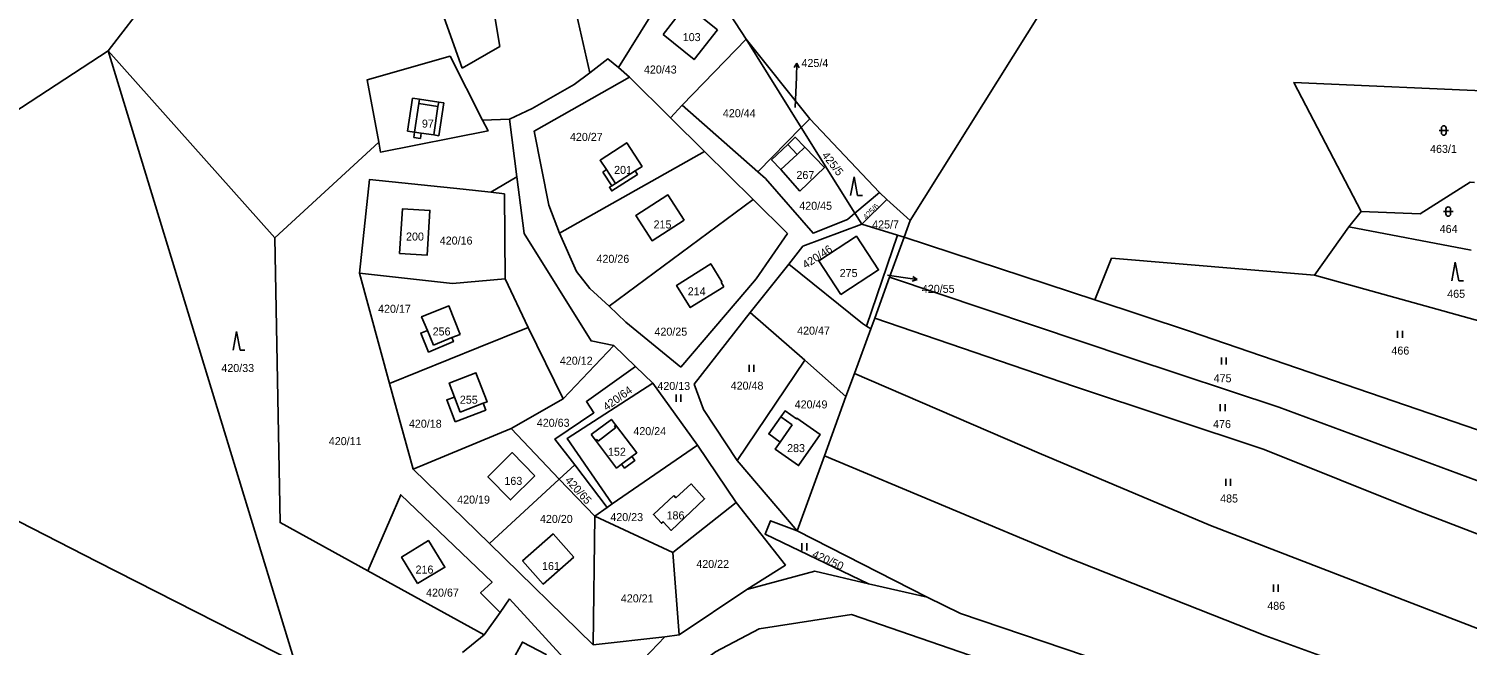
# Model space of a CAD drawing. Extents: x -7483133 to -743169, y -11317770 to -1127091.
# Drawn here: x -748944.8 to -748639.3, y -1130557.3 to -1130426.4 of the extents above; entities that cross this region are included whole.
import ezdxf

# ---------------------------------------------------------------- set-up
doc = ezdxf.new("R2010")
doc.units = 0
for name, color, linetype in [('Hranice parcel', 7, 'Continuous'), ('Parcelní čísla', 7, 'Continuous'), ('Pop  PČ popisy', 7, 'Continuous'), ('Vnitřní kresba', 7, 'Continuous'), ('Značky kultur', 7, 'Continuous')]:
    doc.layers.add(name, color=color, linetype=linetype)

msp = doc.modelspace()

# ---------------------------------------------------------------- linework, layer by layer
at = {"layer": 'Hranice parcel'}
for p, q in [((-748902.2, -1130397.64), (-748927.95, -1130431.02)), ((-748849.48, -1130401.7), (-748844.76, -1130430.14)), ((-748819.51, -1130434.58), (-748804.37, -1130410.14)), ((-748792.44, -1130428.53), (-748804.37, -1130410.14)), ((-748805.98, -1130442.59), (-748792.44, -1130428.53)), ((-748778.89, -1130445.44), (-748792.44, -1130428.53)), ((-748780.72, -1130447.3), (-748792.44, -1130428.53)), ((-748927.95, -1130431.02), (-748892.55, -1130470.72)), ((-748927.95, -1130431.02), (-748888.26, -1130560.86)), ((-748844.76, -1130430.14), (-748852.71, -1130434.75)), ((-748817.21, -1130436.65), (-748819.51, -1130434.58)), ((-748808.51, -1130445.24), (-748817.21, -1130436.65)), ((-748805.98, -1130442.59), (-748808.51, -1130445.24)), ((-748789.95, -1130456.7), (-748805.98, -1130442.59)), ((-748848.41, -1130445.73), (-748842.67, -1130445.58)), ((-748841.12, -1130457.78), (-748842.67, -1130445.58)), ((-748801.29, -1130452.44), (-748808.51, -1130445.24)), ((-748789.95, -1130456.7), (-748780.72, -1130447.3)), ((-748780.72, -1130447.3), (-748778.89, -1130445.44)), ((-748769.34, -1130465.53), (-748780.72, -1130447.3)), ((-748764.11, -1130461.14), (-748778.89, -1130445.44)), ((-748892.55, -1130470.72), (-748870.46, -1130450.45)), ((-748832.08, -1130469.75), (-748801.29, -1130452.44)), ((-748801.29, -1130452.44), (-748790.91, -1130462.62)), ((-748788.31, -1130458.17), (-748789.95, -1130456.7)), ((-748852.5, -1130460.44), (-748846.67, -1130461.06)), ((-748846.67, -1130461.06), (-748841.12, -1130457.78)), ((-748839.58, -1130469.86), (-748841.12, -1130457.78)), ((-748846.67, -1130461.06), (-748843.74, -1130461.37)), ((-748843.74, -1130461.37), (-748843.6, -1130479.46)), ((-748790.91, -1130462.62), (-748821.52, -1130485.28)), ((-748790.91, -1130462.62), (-748783.62, -1130469.82)), ((-748769.34, -1130465.53), (-748764.11, -1130461.14)), ((-748767.88, -1130467.87), (-748762.56, -1130462.59)), ((-748762.56, -1130462.59), (-748764.11, -1130461.14)), ((-748757.6, -1130467.05), (-748762.56, -1130462.59)), ((-748769.34, -1130465.53), (-748770.9, -1130466.83)), ((-748767.88, -1130467.87), (-748769.34, -1130465.53)), ((-748664.43, -1130468.41), (-748661.8, -1130465.15)), ((-748760.27, -1130470.2), (-748767.88, -1130467.87)), ((-748757.6, -1130467.05), (-748758.89, -1130470.62)), ((-748671.7, -1130478.68), (-748664.43, -1130468.41)), ((-748664.43, -1130468.41), (-748638.43, -1130473.4)), ((-748766.84, -1130489.51), (-748760.27, -1130470.2)), ((-748761.98, -1130479.13), (-748758.89, -1130470.62)), ((-748758.89, -1130470.62), (-748760.27, -1130470.2)), ((-748758.89, -1130470.62), (-748718.34, -1130483.88)), ((-748868.14, -1130501.65), (-748874.54, -1130478.26)), ((-748791.56, -1130486.57), (-748783.35, -1130476.32)), ((-748843.6, -1130479.46), (-748838.72, -1130489.81)), ((-748797.15, -1130481.13), (-748797.74, -1130480.18)), ((-748765.12, -1130487.78), (-748761.98, -1130479.13)), ((-748803.45, -1130501.81), (-748791.56, -1130486.57)), ((-748791.56, -1130486.57), (-748779.98, -1130496.71)), ((-748765.94, -1130490.05), (-748765.12, -1130487.78)), ((-748838.72, -1130489.81), (-748831.25, -1130504.91)), ((-748769.41, -1130499.53), (-748765.94, -1130490.05)), ((-748765.94, -1130490.05), (-748766.84, -1130489.51)), ((-748831.25, -1130504.91), (-748820.54, -1130493.62)), ((-748820.54, -1130493.62), (-748815.91, -1130498.09)), ((-748779.98, -1130496.71), (-748794.31, -1130518)), ((-748771.22, -1130504.47), (-748779.98, -1130496.71)), ((-748815.91, -1130498.09), (-748812.25, -1130501.61)), ((-748771.22, -1130504.47), (-748769.41, -1130499.53)), ((-748863.15, -1130519.89), (-748868.14, -1130501.65)), ((-748812.25, -1130501.61), (-748802.76, -1130514.74)), ((-748831.25, -1130504.91), (-748842.3, -1130511.21)), ((-748775.79, -1130517.06), (-748771.22, -1130504.47)), ((-748842.3, -1130511.21), (-748863.15, -1130519.89)), ((-748832.1, -1130521.99), (-748842.3, -1130511.21)), ((-748802.76, -1130514.74), (-748820.87, -1130527.26)), ((-748802.76, -1130514.74), (-748794.57, -1130526.92)), ((-748794.31, -1130518), (-748781.55, -1130532.95)), ((-748781.55, -1130532.95), (-748775.79, -1130517.06)), ((-748846.93, -1130535.69), (-748863.15, -1130519.89)), ((-748832.1, -1130521.99), (-748828.83, -1130518.95)), ((-748828.83, -1130518.95), (-748821.95, -1130528)), ((-748846.93, -1130535.69), (-748832.1, -1130521.99)), ((-748824.58, -1130529.82), (-748832.1, -1130521.99)), ((-748820.87, -1130527.26), (-748821.95, -1130528)), ((-748794.57, -1130526.92), (-748807.97, -1130537.59)), ((-748824.94, -1130557.15), (-748824.58, -1130529.82)), ((-748821.95, -1130528), (-748824.58, -1130529.82)), ((-748807.97, -1130537.59), (-748824.58, -1130529.82)), ((-748754, -1130547.08), (-748781.55, -1130532.95)), ((-748824.94, -1130557.15), (-748846.93, -1130535.69)), ((-748806.63, -1130555.06), (-748807.97, -1130537.59)), ((-748848.06, -1130555.08), (-748872.79, -1130541.46)), ((-748806.63, -1130555.06), (-748792.29, -1130545.43)), ((-748766.4, -1130544.2), (-748754, -1130547.08)), ((-748842.68, -1130547.42), (-748844.69, -1130550.29)), ((-748822.02, -1130569.92), (-748842.68, -1130547.42)), ((-748844.69, -1130550.29), (-748848.06, -1130555.08)), ((-748848.06, -1130555.08), (-748852.67, -1130558.78)), ((-748809.68, -1130555.47), (-748806.63, -1130555.06)), ((-748809.68, -1130555.47), (-748824.94, -1130557.15))]:
    msp.add_line(p, q, dxfattribs=at)
for points in [[(-748668.63, -1130323.88), (-748723.49, -1130412.55), (-748757.6, -1130467.05)], [(-748825.64, -1130435.7), (-748830.6, -1130413.85), (-748827.29, -1130401.09), (-748824.29, -1130394.55), (-748817.71, -1130391.16)], [(-748852.71, -1130434.75), (-748864.73, -1130401.17), (-748858.73, -1130399.01)], [(-748798.53, -1130426.57), (-748805.14, -1130421.28), (-748810.06, -1130427.6)], [(-748810.06, -1130427.6), (-748803.47, -1130432.9), (-748798.53, -1130426.57)], [(-749070.43, -1130467.11), (-748982.99, -1130466.97), (-748927.95, -1130431.02)], [(-748848.41, -1130445.73), (-748855.31, -1130432.18), (-748872.92, -1130437.22), (-748870.46, -1130450.45)], [(-748825.64, -1130435.7), (-748821.76, -1130432.75), (-748819.51, -1130434.58)], [(-748842.67, -1130445.58), (-748837.83, -1130443.26), (-748828.93, -1130438.2), (-748825.64, -1130435.7)], [(-748817.21, -1130436.65), (-748837.42, -1130448.09), (-748834.32, -1130463.8), (-748832.08, -1130469.75)], [(-748661.8, -1130465.15), (-748676.09, -1130437.74), (-748631.31, -1130439.73)], [(-748870.46, -1130450.45), (-748870.08, -1130452.52), (-748847.24, -1130448.03), (-748848.41, -1130445.73)], [(-748822.89, -1130456.78), (-748820.97, -1130459.7), (-748821.47, -1130460.02), (-748820.98, -1130460.78), (-748815.5, -1130457.27), (-748815.97, -1130456.53), (-748814.52, -1130455.58), (-748817.78, -1130450.55), (-748823.43, -1130454.26), (-748822.1, -1130456.26), (-748822.89, -1130456.78)], [(-748781, -1130460.83), (-748775.78, -1130455.82), (-748779.97, -1130451.47), (-748781.98, -1130449.37), (-748783.6, -1130450.93), (-748787.01, -1130454.2), (-748785.04, -1130456.25), (-748781, -1130460.83)], [(-748874.54, -1130478.26), (-748872.39, -1130458.34), (-748852.5, -1130460.44)], [(-748770.9, -1130466.83), (-748778.22, -1130469.78), (-748788.31, -1130458.17)], [(-748661.8, -1130465.15), (-748649.27, -1130465.67), (-748638.63, -1130458.96), (-748637.75, -1130459.01)], [(-748805.57, -1130466.96), (-748809.03, -1130461.64), (-748815.82, -1130465.97), (-748812.39, -1130471.35), (-748805.57, -1130466.96)], [(-748866.07, -1130474.04), (-748860.16, -1130474.4), (-748859.58, -1130464.94), (-748865.44, -1130464.59), (-748866.07, -1130474.04)], [(-749070.43, -1130467.11), (-749012.81, -1130497.2), (-748930.34, -1130539.46), (-748888.26, -1130560.86)], [(-748783.35, -1130476.32), (-748780.36, -1130472.52), (-748767.88, -1130467.87)], [(-748892.55, -1130470.72), (-748891.42, -1130531.21), (-748872.79, -1130541.46)], [(-748820.54, -1130493.62), (-748825.34, -1130492.64), (-748839.58, -1130469.86)], [(-748821.52, -1130485.28), (-748825.63, -1130481.5), (-748828.48, -1130477.93), (-748832.08, -1130469.75)], [(-748783.62, -1130469.82), (-748790.29, -1130479.46), (-748792.26, -1130481.76), (-748806.27, -1130498.24)], [(-748772.28, -1130482.78), (-748764.3, -1130477.55), (-748768.99, -1130470.4), (-748776.95, -1130475.63), (-748772.28, -1130482.78)], [(-748718.34, -1130483.88), (-748714.81, -1130475.07), (-748671.7, -1130478.68)], [(-748874.54, -1130478.26), (-748854.82, -1130480.43), (-748843.6, -1130479.46)], [(-748797.74, -1130480.18), (-748797.55, -1130480.06), (-748799.94, -1130476.26), (-748807.21, -1130480.86), (-748804.28, -1130485.57), (-748797.15, -1130481.13)], [(-748783.35, -1130476.32), (-748767.74, -1130488.96), (-748766.84, -1130489.51)], [(-748671.7, -1130478.68), (-748633.74, -1130489.24), (-748618.21, -1130483.5)], [(-748761.98, -1130479.13), (-748710.91, -1130496.25), (-748679.26, -1130506.7), (-748621.93, -1130527.97)], [(-748718.34, -1130483.88), (-748698.29, -1130490.59), (-748629.43, -1130514.15)], [(-748853.13, -1130491.26), (-748855.56, -1130485.21), (-748861.36, -1130487.49), (-748860.13, -1130490.42), (-748861.54, -1130490.99), (-748859.85, -1130495.02), (-748854.59, -1130492.79), (-748854.96, -1130491.92), (-748853.13, -1130491.26)], [(-748806.27, -1130498.24), (-748817.98, -1130488.65), (-748821.52, -1130485.28)], [(-748765.12, -1130487.78), (-748722.68, -1130502.34), (-748682.4, -1130515.73), (-748650.26, -1130528.57), (-748607.86, -1130544.88)], [(-748868.14, -1130501.65), (-748849.28, -1130494.06), (-748838.72, -1130489.81)], [(-748854.2, -1130509.79), (-748847.71, -1130507.33), (-748848.25, -1130505.89), (-748847.44, -1130505.58), (-748849.81, -1130499.38), (-748855.49, -1130501.59), (-748854.37, -1130504.59), (-748856.01, -1130505.15), (-748854.2, -1130509.79)], [(-748828.83, -1130518.95), (-748833.02, -1130513.48), (-748824.76, -1130507.89), (-748826.36, -1130505.51), (-748815.91, -1130498.09)], [(-748769.41, -1130499.53), (-748730.21, -1130516.5), (-748693.83, -1130531.8), (-748627.18, -1130557.56), (-748603.84, -1130566.17), (-748577.63, -1130576.56)], [(-748812.25, -1130501.61), (-748830.46, -1130513.37), (-748820.87, -1130527.26)], [(-748794.31, -1130518), (-748801.5, -1130507.17), (-748803.45, -1130501.81)], [(-748816.7, -1130517.18), (-748815.67, -1130516.4), (-748820.14, -1130510.48), (-748821.04, -1130509.29), (-748825.32, -1130512.52)], [(-748785.03, -1130508.74), (-748784.15, -1130507.49), (-748781.75, -1130509.19), (-748781.63, -1130509.04), (-748776.67, -1130512.52), (-748781.3, -1130519.11), (-748786.27, -1130515.61), (-748785.21, -1130514.11), (-748787.62, -1130512.4), (-748785.03, -1130508.74)], [(-748825.32, -1130512.52), (-748824.39, -1130513.73), (-748819.95, -1130519.63), (-748818.86, -1130518.81), (-748818.22, -1130519.65), (-748816.06, -1130518.02), (-748816.7, -1130517.18)], [(-748837.33, -1130521.27), (-748842.14, -1130516.36), (-748847.28, -1130521.51), (-748842.48, -1130526.4), (-748837.33, -1130521.27)], [(-748775.79, -1130517.06), (-748724.37, -1130538.57), (-748682.28, -1130555.19), (-748652.69, -1130565.92), (-748602.7, -1130584.94), (-748579.32, -1130593.13)], [(-748807.77, -1130525.47), (-748812.13, -1130529.47), (-748810.42, -1130531.37), (-748810.07, -1130531.04), (-748808.34, -1130532.87), (-748801.24, -1130526.14), (-748804.12, -1130523), (-748807.33, -1130525.95), (-748807.77, -1130525.47)], [(-748872.79, -1130541.46), (-748865.77, -1130525.3), (-748846.38, -1130543.87), (-748848.82, -1130546.16), (-748844.69, -1130550.29)], [(-748794.57, -1130526.92), (-748784.09, -1130540.23), (-748792.29, -1130545.43)], [(-748829.04, -1130538.57), (-748833.41, -1130533.62), (-748839.91, -1130539.35), (-748835.51, -1130544.26), (-748829.04, -1130538.57)], [(-748766.4, -1130544.2), (-748788.4, -1130533.64), (-748787.24, -1130530.81), (-748781.55, -1130532.95)], [(-748862.21, -1130544.17), (-748856.41, -1130540.69), (-748859.91, -1130535.03), (-748865.59, -1130538.53), (-748862.21, -1130544.17)], [(-748792.29, -1130545.43), (-748777.8, -1130541.55), (-748766.4, -1130544.2)], [(-748694.25, -1130568.39), (-748746.89, -1130550.49), (-748754, -1130547.08)], [(-748671.54, -1130609.27), (-748689.21, -1130588.28), (-748698.85, -1130579.03), (-748711.73, -1130570.87), (-748770.07, -1130550.7), (-748789.66, -1130553.8), (-748798.91, -1130558.69), (-748806.83, -1130564.57), (-748827.25, -1130594.48)], [(-748843.04, -1130562.3), (-748837.93, -1130565), (-748834.89, -1130559.25), (-748839.93, -1130556.59), (-748843.04, -1130562.3)], [(-748822.02, -1130569.92), (-748818.59, -1130564.8), (-748809.68, -1130555.47)]]:
    msp.add_lwpolyline(points, dxfattribs=at)
at = {"layer": 'Pop  PČ popisy'}
for p, q in [((-748781.66, -1130433.62), (-748782.19, -1130434.6)), ((-748781.76, -1130436.62), (-748781.66, -1130433.62)), ((-748781.66, -1130433.62), (-748781.19, -1130434.64)), ((-748781.98, -1130443.1), (-748781.76, -1130436.62)), ((-748762.38, -1130478.64), (-748759.07, -1130479.14)), ((-748759.07, -1130479.14), (-748756.11, -1130479.61)), ((-748756.11, -1130479.61), (-748757.17, -1130479.95)), ((-748756.11, -1130479.61), (-748757.02, -1130478.96))]:
    msp.add_line(p, q, dxfattribs=at)
at = {"layer": 'Vnitřní kresba'}
for p, q in [((-748864.32, -1130448.09), (-748863.29, -1130441.1)), ((-748861.79, -1130441.32), (-748863.29, -1130441.1)), ((-748861.79, -1130441.32), (-748861.93, -1130442.25)), ((-748857.7, -1130441.93), (-748861.79, -1130441.32)), ((-748857.89, -1130442.87), (-748857.7, -1130441.93)), ((-748856.66, -1130442.08), (-748857.7, -1130441.93)), ((-748857.69, -1130449.07), (-748856.66, -1130442.08)), ((-748861.93, -1130442.25), (-748862.83, -1130448.3)), ((-748861.93, -1130442.25), (-748857.89, -1130442.87)), ((-748858.72, -1130448.9), (-748857.89, -1130442.87)), ((-748862.83, -1130448.3), (-748864.32, -1130448.09)), ((-748863, -1130449.44), (-748862.83, -1130448.3)), ((-748863, -1130449.44), (-748861.6, -1130449.68)), ((-748862.83, -1130448.3), (-748861.43, -1130448.51)), ((-748861.43, -1130448.51), (-748861.6, -1130449.68)), ((-748858.72, -1130448.9), (-748861.43, -1130448.51)), ((-748857.69, -1130449.07), (-748858.72, -1130448.9)), ((-748783.6, -1130450.93), (-748781.59, -1130453.02)), ((-748781.59, -1130453.02), (-748785.04, -1130456.25)), ((-748781.59, -1130453.02), (-748779.97, -1130451.47)), ((-748822.1, -1130456.26), (-748820.16, -1130459.19)), ((-748820.16, -1130459.19), (-748815.97, -1130456.53)), ((-748820.97, -1130459.7), (-748820.16, -1130459.19)), ((-748860.13, -1130490.42), (-748858.82, -1130493.54)), ((-748858.82, -1130493.54), (-748854.96, -1130491.92)), ((-748853.18, -1130507.76), (-748854.37, -1130504.59)), ((-748853.18, -1130507.76), (-748848.25, -1130505.89)), ((-748785.03, -1130508.74), (-748782.61, -1130510.45)), ((-748820.09, -1130511.05), (-748823.86, -1130513.93)), ((-748820.14, -1130510.48), (-748820.38, -1130510.66)), ((-748820.38, -1130510.66), (-748820.09, -1130511.05)), ((-748782.61, -1130510.45), (-748785.21, -1130514.11)), ((-748824.15, -1130513.55), (-748824.39, -1130513.73)), ((-748823.86, -1130513.93), (-748824.15, -1130513.55)), ((-748816.7, -1130517.18), (-748818.86, -1130518.81))]:
    msp.add_line(p, q, dxfattribs=at)
at = {"layer": 'Značky kultur'}
for p, q in [((-748645.25, -1130447.95), (-748643.25, -1130447.95)), ((-748644.75, -1130447.45), (-748644.75, -1130448.45)), ((-748643.75, -1130448.45), (-748643.75, -1130447.45)), ((-748769.49, -1130457.79), (-748770.24, -1130461.79)), ((-748768.74, -1130461.79), (-748769.49, -1130457.79)), ((-748768.74, -1130461.79), (-748767.74, -1130461.79)), ((-748644.29, -1130465.16), (-748642.29, -1130465.16)), ((-748643.79, -1130464.66), (-748643.79, -1130465.66)), ((-748642.79, -1130465.66), (-748642.79, -1130464.66)), ((-748641.81, -1130475.88), (-748642.56, -1130479.88)), ((-748641.06, -1130479.88), (-748641.81, -1130475.88)), ((-748641.06, -1130479.88), (-748640.06, -1130479.88)), ((-748900.64, -1130490.63), (-748901.39, -1130494.63)), ((-748899.89, -1130494.63), (-748900.64, -1130490.63)), ((-748654.05, -1130491.99), (-748654.05, -1130490.49)), ((-748653.05, -1130491.99), (-748653.05, -1130490.49)), ((-748899.89, -1130494.63), (-748898.89, -1130494.63)), ((-748691.45, -1130497.67), (-748691.45, -1130496.17)), ((-748690.45, -1130497.67), (-748690.45, -1130496.17)), ((-748791.81, -1130499.23), (-748791.81, -1130497.73)), ((-748790.81, -1130499.23), (-748790.81, -1130497.73)), ((-748807.29, -1130505.55), (-748807.29, -1130504.05)), ((-748806.29, -1130505.55), (-748806.29, -1130504.05)), ((-748691.71, -1130507.54), (-748691.71, -1130506.04)), ((-748690.71, -1130507.54), (-748690.71, -1130506.04)), ((-748690.52, -1130523.4), (-748690.52, -1130521.9)), ((-748689.52, -1130523.4), (-748689.52, -1130521.9)), ((-748780.56, -1130537.12), (-748780.56, -1130535.62)), ((-748779.56, -1130537.12), (-748779.56, -1130535.62)), ((-748680.4, -1130545.89), (-748680.4, -1130544.39)), ((-748679.4, -1130545.89), (-748679.4, -1130544.39))]:
    msp.add_line(p, q, dxfattribs=at)
for centre, start, end in [((-748644.25, -1130447.45), 0, 180), ((-748644.25, -1130448.45), 180, 359.9879), ((-748643.29, -1130464.66), 0, 180), ((-748643.29, -1130465.66), 180, 359.9879)]:
    msp.add_arc(centre, 0.5, start, end, dxfattribs=at)

# ---------------------------------------------------------------- texts
at = {"layer": 'Parcelní čísla'}
for s, p in [('103', (-748805.88, -1130428.97)), ('425/4', (-748780.66, -1130434.47)), ('420/43', (-748814.13, -1130435.85)), ('420/44', (-748797.36, -1130445.13)), ('97', (-748861.28, -1130447.34)), ('420/27', (-748829.84, -1130450.16)), ('463/1', (-748647.16, -1130452.71)), ('201', (-748820.46, -1130457.17)), ('267', (-748781.74, -1130458.25)), ('420/45', (-748781.13, -1130464.79)), ('200', (-748864.65, -1130471.32)), ('215', (-748812.08, -1130468.75)), ('425/7', (-748765.65, -1130468.76)), ('464', (-748645.12, -1130469.71)), ('420/16', (-748857.49, -1130472.18)), ('420/26', (-748824.2, -1130476.05)), ('275', (-748772.56, -1130479.08)), ('214', (-748804.83, -1130482.96)), ('420/55', (-748755.1, -1130482.43)), ('465', (-748643.52, -1130483.48)), ('420/17', (-748870.59, -1130486.66)), ('256', (-748859, -1130491.48)), ('420/25', (-748811.89, -1130491.52)), ('420/47', (-748781.59, -1130491.3)), ('466', (-748655.37, -1130495.54)), ('420/12', (-748831.98, -1130497.69)), ('420/33', (-748903.87, -1130499.24)), ('475', (-748693.13, -1130501.42)), ('420/13', (-748811.27, -1130503.05)), ('420/48', (-748795.7, -1130502.98)), ('255', (-748853.22, -1130505.97)), ('420/49', (-748782.11, -1130506.97)), ('420/18', (-748864.04, -1130511.07)), ('420/63', (-748836.88, -1130510.87)), ('420/24', (-748816.37, -1130512.65)), ('476', (-748693.25, -1130511.15)), ('420/11', (-748881.05, -1130514.77)), ('152', (-748821.76, -1130517.02)), ('283', (-748783.72, -1130516.25)), ('163', (-748843.76, -1130523.21)), ('420/19', (-748853.79, -1130527.18)), ('485', (-748691.75, -1130526.95)), ('420/20', (-748836.21, -1130531.29)), ('420/23', (-748821.26, -1130530.9)), ('186', (-748809.32, -1130530.54)), ('161', (-748835.77, -1130541.29)), ('420/22', (-748803, -1130540.85)), ('216', (-748862.63, -1130542.04)), ('420/67', (-748860.39, -1130546.94)), ('420/21', (-748819.03, -1130548.16)), ('486', (-748681.74, -1130549.74))]:
    msp.add_text(s, height=1.7, dxfattribs=at).set_placement(p)
for s, height, rotation, p in [('425/5', 1.7, 308, (-748776.44, -1130453.27)), ('425/6', 1.14, 45, (-748766.9, -1130466.94)), ('420/46', 1.7, 33, (-748779.77, -1130477.36)), ('420/64', 1.7, 36, (-748822.05, -1130507.55)), ('420/65', 1.7, 312, (-748831, -1130522.33)), ('420/50', 1.7, 336, (-748778.55, -1130538.53))]:
    msp.add_text(s, height=height, rotation=rotation, dxfattribs=at).set_placement(p)

doc.saveas('drawing.dxf')
